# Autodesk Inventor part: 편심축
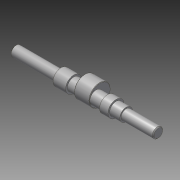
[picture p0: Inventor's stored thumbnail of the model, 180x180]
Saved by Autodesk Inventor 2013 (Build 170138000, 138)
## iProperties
Company: 한국ATC센터
Created: 2014-02
Part Number: 편심축
Document SubType Name: Modeling
Designer: KYOUNG IL JANG
Density: 7.86 g/cm^3
Mass: 246.092 g
Surface Area: 95.1288 cm^2
Volume: 31.3094 cm^3
Material: 강, 연강
Vendor: CBT Solutions
Author: KYOUNG IL JANG
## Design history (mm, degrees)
sketch "스케치1"
  geometry: L1 (-84.5, 0)-(84.5, 0); L2 (-84.5, 0)-(-84.5, 6); L3 (-84.5, 6)-(-30.5, 6); L4 (-30.5, 6)-(-30.5, 9.5); L5 (-30.5, 9.5)-(-15.5, 9.5); L6 (-15.5, 9.5)-(-15.5, 7.5); L7 (-15.5, 7.5)-(46.5, 7.5); L8 (84.5, 6)-(84.5, 0); L9 (34.5, 7.5)-(34.5, 9.5); L10 (34.5, 9.5)-(24.5, 9.5); L11 (24.5, 9.5)-(24.5, 7.5); L12 (46.5, 7.5)-(46.5, 6); L13 (46.5, 6)-(84.5, 6); 2 further points
  constraints: 26 end point, 6 parallel, 6 perpendicular, 2 point on line, 1 coincident, 1 horizontal, 1 midpoint
  dimensions: "d1" = 12 diameter of L3 L1; "d2" = 15 diameter of L7 L1; "d4" = 15 distance of L4.end L5.end; "d5" = 19 diameter of L5 L1; "d24" = 10 distance of L9.end L10.end; "d25" = 19 diameter of L10 L1; "d27" = 40 distance between parallel lines of L11 L6; "d28" = 54 distance of L2.end L3.end; "d29" = 50 distance between parallel lines of L8 L9; "d41" = 38 distance between parallel lines of L8 L12; "d42" = 12 diameter of L13 L1
revolve "회전1" stored, may be unused: angle "d6" = 90 deg
node "작업 평면1"
sketch "스케치2"
  geometry: C1 r 7.5 at (0, 0) reference; C2 r 12.5 at (0, 4.5); 1 further point
  constraints: 1 centre point, 1 vertical alignment
  dimensions: "d8" = 4.5 distance of point (0, 0) C2.centre; "d9" = 25 diameter of C2
extrude "돌출1" join sketch "스케치2" distance "d10" = 18; taper "d11" = 0 deg
chamfer "모따기1" distance "d12" = 1; stored, may be unused: second distance "d13" = 2, angle "d14" = 45 deg
chamfer "모따기2" distance "d15" = 0.5; stored, may be unused: second distance "d16" = 2, angle "d17" = 45 deg
node "작업 평면2"
sketch "스케치3"
  geometry: L1 (4, -2)-(18, -2); L2 (18, 2)-(4, 2); L3 (27, 5)-(27, -5) reference; L4 (-137, -2)-(-123, -2); L5 (-123, 2)-(-137, 2); L6 (-142, -5)-(-142, 5) reference; A1 r 2 centre (18, 0) between (18, -2) and (18, 2); A2 r 2 centre (4, 0) between (4, 2) and (4, -2); A3 r 2 centre (-123, 0) between (-123, -2) and (-123, 2); A4 r 2 centre (-137, 0) between (-137, 2) and (-137, -2); 2 further points
  constraints: 8 end point, 8 point on circle, 8 tangent, 4 centre point, 2 horizontal, 2 horizontal alignment, 2 parallel, 1 midpoint
  dimensions: "d18" = 7 distance edge to line of A1 L3; "d19" = 4 distance between parallel lines of L2 L1; "d20" = 18 dimension on A1 A2; "d43" = 4 distance between parallel lines of L5 L4; "d44" = 18 dimension on A3 A4; "d45" = 3 distance edge to line of A4 L6
extrude "돌출2" cut sketch "스케치3" distance "d21" = 2.5; taper "d22" = 0 deg
revolve "회전2" stored, may be unused: angle "d26" = 90 deg
node "솔리드1"
other parameters: "d7" = 8.5
